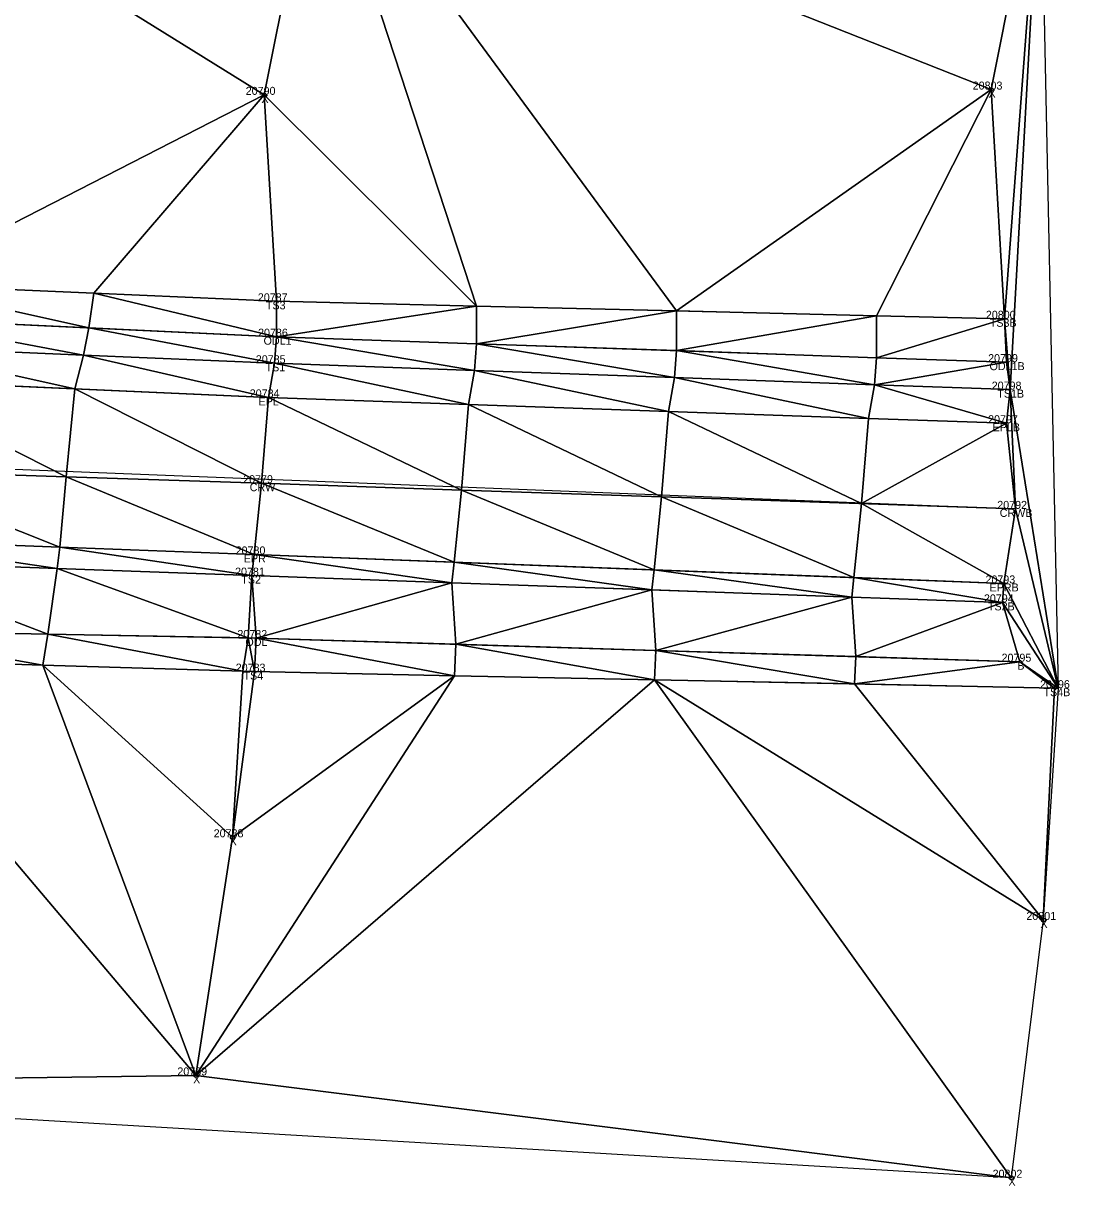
# Model space of a CAD drawing. Extents: x 1966740 to 1969291, y 1117379 to 1118460.
# Drawn here: x 1969160.5 to 1969291.2, y 1117800.2 to 1117945.4 of the extents above; entities that cross this region are included whole.
import ezdxf

# ---------------------------------------------------------------- set-up
doc = ezdxf.new("R2010")
doc.units = 0
for name, color, linetype in [('Level 1', 7, 'Continuous'), ('Level 3', 7, 'Continuous'), ('Level 30', 7, 'Continuous'), ('Level 35', 7, 'Continuous'), ('Level 50', 7, 'Continuous'), ('Level 52', 7, 'Continuous'), ('Level 53', 7, 'Continuous'), ('Level 56', 7, 'Continuous'), ('Level 6', 7, 'Continuous'), ('Level 62', 7, 'Continuous')]:
    doc.layers.add(name, color=color, linetype=linetype)

msp = doc.modelspace()

# ---------------------------------------------------------------- linework, layer by layer
at = {"layer": 'Level 1'}
msp.add_line((1968120.33, 1117930.94), (1969279.02, 1117884.95), dxfattribs=at)
at = {"layer": 'Level 3'}
for points in [[(1968531.49, 1117931.42), (1968682.06, 1117924.3), (1968783.42, 1117919.17), (1968888.7, 1117914.33), (1968991.06, 1117912.02), (1969093.07, 1117907.16), (1969191.83, 1117902.92), (1969283.72, 1117899.63)], [(1968530.54, 1117925.7), (1968681.97, 1117919.01), (1968783.23, 1117915.36), (1968888.64, 1117911.44), (1968991.22, 1117907.09), (1969091.98, 1117903.06), (1969191.09, 1117898.66), (1969283.27, 1117895.43)], [(1968882.13, 1117923.29), (1968991.72, 1117919.56), (1969094.35, 1117914.97), (1969192.08, 1117910.66), (1969282.99, 1117908.48)], [(1968529.36, 1117916.3), (1968681.48, 1117908.5), (1968781.89, 1117904.51), (1968887.49, 1117900.39), (1968989.06, 1117896.4), (1969090.87, 1117891.24), (1969190.23, 1117887.94), (1969284.4, 1117884.73)], [(1968527.82, 1117906.41), (1968680.79, 1117899.07), (1968781.71, 1117895.37), (1968887.86, 1117891.84), (1968988.65, 1117888.23), (1969090.1, 1117882.83), (1969189.3, 1117879.04), (1969282.94, 1117875.42)], [(1968528.99, 1117899.6), (1968680.45, 1117894.84), (1968781.74, 1117892.71), (1968887.7, 1117888.94), (1968987.81, 1117885.08), (1969089.75, 1117880.01), (1969189.02, 1117876.39), (1969282.76, 1117873.05)], [(1968528.68, 1117880.51), (1968680.3, 1117884.55), (1968781.05, 1117880.46), (1968887.57, 1117875.57), (1968986, 1117872.85), (1969087.95, 1117867.56), (1969189.32, 1117864.4), (1969289.73, 1117862.33)]]:
    msp.add_lwpolyline(points, dxfattribs=at)
at = {"layer": 'Level 30'}
for centre in [(1969190.53, 1117936.45), (1969281.34, 1117937.11), (1969186.57, 1117843.71), (1969287.84, 1117833.38), (1969182.01, 1117813.96), (1969283.84, 1117801.18)]:
    msp.add_circle(centre, 0.25, dxfattribs=at)
at = {"layer": 'Level 35'}
for points in [[(1969111.1, 1117985.78), (1969197.32, 1117970.35), (1969190.53, 1117936.45)], [(1969111.1, 1117985.78), (1969190.53, 1117936.45), (1969144.29, 1117912.77)], [(1969190.53, 1117936.45), (1969197.32, 1117970.35), (1969217.07, 1117910.06)], [(1969197.32, 1117970.35), (1969287.52, 1117968.07), (1969281.34, 1117937.11)], [(1969197.32, 1117970.35), (1969281.34, 1117937.11), (1969242.05, 1117909.46)], [(1969197.32, 1117970.35), (1969242.05, 1117909.46), (1969217.07, 1117910.06)], [(1969281.34, 1117937.11), (1969287.52, 1117968.07), (1969282.99, 1117908.48)], [(1969282.99, 1117908.48), (1969287.52, 1117968.07), (1969283.72, 1117899.63)], [(1969283.72, 1117899.63), (1969287.52, 1117968.07), (1969289.73, 1117862.33)], [(1969144.29, 1117912.77), (1969190.53, 1117936.45), (1969169.25, 1117911.66)], [(1969169.25, 1117911.66), (1969190.53, 1117936.45), (1969192.08, 1117910.66)], [(1969190.53, 1117936.45), (1969217.07, 1117910.06), (1969192.08, 1117910.66)], [(1969242.05, 1117909.46), (1969281.34, 1117937.11), (1969267.03, 1117908.86)], [(1969267.03, 1117908.86), (1969281.34, 1117937.11), (1969282.99, 1117908.48)], [(1969143.7, 1117908.53), (1969144.29, 1117912.77), (1969168.66, 1117907.35)], [(1969144.29, 1117912.77), (1969169.25, 1117911.66), (1969168.66, 1117907.35)], [(1969168.66, 1117907.35), (1969169.25, 1117911.66), (1969192.08, 1117906.24)], [(1969169.25, 1117911.66), (1969192.08, 1117910.66), (1969192.08, 1117906.24)], [(1969192.08, 1117906.24), (1969192.08, 1117910.66), (1969217.07, 1117910.06)], [(1969192.08, 1117906.24), (1969217.07, 1117910.06), (1969217.06, 1117905.37)], [(1969217.06, 1117905.37), (1969217.07, 1117910.06), (1969242.05, 1117909.46)], [(1969143.01, 1117905.02), (1969143.7, 1117908.53), (1969167.98, 1117903.95)], [(1969143.7, 1117908.53), (1969168.66, 1117907.35), (1969167.98, 1117903.95)], [(1969217.06, 1117905.37), (1969242.05, 1117909.46), (1969242.03, 1117904.5)], [(1969242.03, 1117904.5), (1969242.05, 1117909.46), (1969267.03, 1117908.86)], [(1969242.03, 1117904.5), (1969267.03, 1117908.86), (1969267.01, 1117903.62)], [(1969267.01, 1117903.62), (1969267.03, 1117908.86), (1969282.99, 1117908.48)], [(1969167.98, 1117903.95), (1969168.66, 1117907.35), (1969191.83, 1117902.92)], [(1969168.66, 1117907.35), (1969192.08, 1117906.24), (1969191.83, 1117902.92)], [(1969267.01, 1117903.62), (1969282.99, 1117908.48), (1969283.24, 1117903.06)], [(1969282.99, 1117908.48), (1969283.72, 1117899.63), (1969283.24, 1117903.06)], [(1969191.83, 1117902.92), (1969192.08, 1117906.24), (1969216.81, 1117902.03)], [(1969192.08, 1117906.24), (1969217.06, 1117905.37), (1969216.81, 1117902.03)], [(1969141.92, 1117900.84), (1969143.01, 1117905.02), (1969166.89, 1117899.73)], [(1969143.01, 1117905.02), (1969167.98, 1117903.95), (1969166.89, 1117899.73)], [(1969216.81, 1117902.03), (1969217.06, 1117905.37), (1969241.78, 1117901.13)], [(1969217.06, 1117905.37), (1969242.03, 1117904.5), (1969241.78, 1117901.13)], [(1969241.78, 1117901.13), (1969242.03, 1117904.5), (1969266.76, 1117900.24)], [(1969242.03, 1117904.5), (1969267.01, 1117903.62), (1969266.76, 1117900.24)], [(1969166.89, 1117899.73), (1969167.98, 1117903.95), (1969191.09, 1117898.66)], [(1969167.98, 1117903.95), (1969191.83, 1117902.92), (1969191.09, 1117898.66)], [(1969191.09, 1117898.66), (1969191.83, 1117902.92), (1969216.07, 1117897.78)], [(1969191.83, 1117902.92), (1969216.81, 1117902.03), (1969216.07, 1117897.78)], [(1969266.76, 1117900.24), (1969267.01, 1117903.62), (1969283.24, 1117903.06)], [(1969266.76, 1117900.24), (1969283.24, 1117903.06), (1969283.72, 1117899.63)], [(1969216.07, 1117897.78), (1969216.81, 1117902.03), (1969241.04, 1117896.91)], [(1969216.81, 1117902.03), (1969241.78, 1117901.13), (1969241.04, 1117896.91)], [(1969140.83, 1117889.58), (1969141.92, 1117900.84), (1969165.8, 1117888.75)], [(1969141.92, 1117900.84), (1969166.89, 1117899.73), (1969165.8, 1117888.75)], [(1969241.04, 1117896.91), (1969241.78, 1117901.13), (1969266.02, 1117896.03)], [(1969241.78, 1117901.13), (1969266.76, 1117900.24), (1969266.02, 1117896.03)], [(1969266.02, 1117896.03), (1969266.76, 1117900.24), (1969283.27, 1117895.43)], [(1969266.76, 1117900.24), (1969283.72, 1117899.63), (1969283.27, 1117895.43)], [(1969165.8, 1117888.75), (1969166.89, 1117899.73), (1969190.23, 1117887.94)], [(1969166.89, 1117899.73), (1969191.09, 1117898.66), (1969190.23, 1117887.94)], [(1969190.23, 1117887.94), (1969191.09, 1117898.66), (1969215.2, 1117887.09)], [(1969191.09, 1117898.66), (1969216.07, 1117897.78), (1969215.2, 1117887.09)], [(1969283.27, 1117895.43), (1969283.72, 1117899.63), (1969284.4, 1117884.73)], [(1969283.72, 1117899.63), (1969289.73, 1117862.33), (1969284.4, 1117884.73)], [(1969215.2, 1117887.09), (1969216.07, 1117897.78), (1969240.18, 1117886.24)], [(1969216.07, 1117897.78), (1969241.04, 1117896.91), (1969240.18, 1117886.24)], [(1969240.18, 1117886.24), (1969241.04, 1117896.91), (1969265.15, 1117885.39)], [(1969241.04, 1117896.91), (1969266.02, 1117896.03), (1969265.15, 1117885.39)], [(1969265.15, 1117885.39), (1969266.02, 1117896.03), (1969283.27, 1117895.43)], [(1969265.15, 1117885.39), (1969283.27, 1117895.43), (1969284.4, 1117884.73)], [(1969140.05, 1117880.92), (1969140.83, 1117889.58), (1969165.02, 1117879.97)], [(1969140.83, 1117889.58), (1969165.8, 1117888.75), (1969165.02, 1117879.97)], [(1969165.02, 1117879.97), (1969165.8, 1117888.75), (1969189.3, 1117879.04)], [(1969165.8, 1117888.75), (1969190.23, 1117887.94), (1969189.3, 1117879.04)], [(1969189.3, 1117879.04), (1969190.23, 1117887.94), (1969214.27, 1117878.07)], [(1969190.23, 1117887.94), (1969215.2, 1117887.09), (1969214.27, 1117878.07)], [(1969214.27, 1117878.07), (1969215.2, 1117887.09), (1969239.24, 1117877.11)], [(1969215.2, 1117887.09), (1969240.18, 1117886.24), (1969239.24, 1117877.11)], [(1969239.24, 1117877.11), (1969240.18, 1117886.24), (1969264.21, 1117876.15)], [(1969240.18, 1117886.24), (1969265.15, 1117885.39), (1969264.21, 1117876.15)], [(1969264.21, 1117876.15), (1969265.15, 1117885.39), (1969282.94, 1117875.42)], [(1969265.15, 1117885.39), (1969284.4, 1117884.73), (1969282.94, 1117875.42)], [(1969282.94, 1117875.42), (1969284.4, 1117884.73), (1969289.73, 1117862.33)], [(1969139.71, 1117878.19), (1969140.05, 1117880.92), (1969164.69, 1117877.28)], [(1969140.05, 1117880.92), (1969165.02, 1117879.97), (1969164.69, 1117877.28)], [(1969164.69, 1117877.28), (1969165.02, 1117879.97), (1969189.02, 1117876.39)], [(1969165.02, 1117879.97), (1969189.3, 1117879.04), (1969189.02, 1117876.39)], [(1969138.55, 1117869.57), (1969139.71, 1117878.19), (1969163.54, 1117869.09)], [(1969139.71, 1117878.19), (1969164.69, 1117877.28), (1969163.54, 1117869.09)], [(1969189.02, 1117876.39), (1969189.3, 1117879.04), (1969213.99, 1117875.5)], [(1969189.3, 1117879.04), (1969214.27, 1117878.07), (1969213.99, 1117875.5)], [(1969213.99, 1117875.5), (1969214.27, 1117878.07), (1969238.96, 1117874.61)], [(1969214.27, 1117878.07), (1969239.24, 1117877.11), (1969238.96, 1117874.61)], [(1969163.54, 1117869.09), (1969164.69, 1117877.28), (1969188.53, 1117868.61)], [(1969164.69, 1117877.28), (1969189.02, 1117876.39), (1969188.53, 1117868.61)], [(1969238.96, 1117874.61), (1969239.24, 1117877.11), (1969263.93, 1117873.72)], [(1969239.24, 1117877.11), (1969264.21, 1117876.15), (1969263.93, 1117873.72)], [(1969188.53, 1117868.61), (1969189.02, 1117876.39), (1969189.53, 1117868.6)], [(1969189.02, 1117876.39), (1969213.99, 1117875.5), (1969189.53, 1117868.6)], [(1969189.53, 1117868.6), (1969213.99, 1117875.5), (1969214.5, 1117867.82)], [(1969213.99, 1117875.5), (1969238.96, 1117874.61), (1969214.5, 1117867.82)], [(1969263.93, 1117873.72), (1969264.21, 1117876.15), (1969282.76, 1117873.05)], [(1969264.21, 1117876.15), (1969282.94, 1117875.42), (1969282.76, 1117873.05)], [(1969282.76, 1117873.05), (1969282.94, 1117875.42), (1969289.73, 1117862.33)], [(1969214.5, 1117867.82), (1969238.96, 1117874.61), (1969239.48, 1117867.05)], [(1969238.96, 1117874.61), (1969263.93, 1117873.72), (1969239.48, 1117867.05)], [(1969239.48, 1117867.05), (1969263.93, 1117873.72), (1969264.46, 1117866.28)], [(1969263.93, 1117873.72), (1969282.76, 1117873.05), (1969264.46, 1117866.28)], [(1969264.46, 1117866.28), (1969282.76, 1117873.05), (1969284.94, 1117865.64)], [(1969282.76, 1117873.05), (1969289.73, 1117862.33), (1969284.94, 1117865.64)], [(1969137.91, 1117866), (1969138.55, 1117869.57), (1969162.89, 1117865.22)], [(1969138.55, 1117869.57), (1969163.54, 1117869.09), (1969162.89, 1117865.22)], [(1969162.89, 1117865.22), (1969163.54, 1117869.09), (1969187.88, 1117864.44)], [(1969163.54, 1117869.09), (1969188.53, 1117868.61), (1969187.88, 1117864.44)], [(1969187.88, 1117864.44), (1969188.53, 1117868.61), (1969189.32, 1117864.4)], [(1969188.53, 1117868.61), (1969189.53, 1117868.6), (1969189.32, 1117864.4)], [(1969189.32, 1117864.4), (1969189.53, 1117868.6), (1969214.3, 1117863.88)], [(1969189.53, 1117868.6), (1969214.5, 1117867.82), (1969214.3, 1117863.88)], [(1969214.3, 1117863.88), (1969214.5, 1117867.82), (1969239.29, 1117863.37)], [(1969214.5, 1117867.82), (1969239.48, 1117867.05), (1969239.29, 1117863.37)], [(1969239.29, 1117863.37), (1969239.48, 1117867.05), (1969264.27, 1117862.86)], [(1969239.48, 1117867.05), (1969264.46, 1117866.28), (1969264.27, 1117862.86)], [(1969089.15, 1117812.7), (1969137.91, 1117866), (1969182.01, 1117813.96)], [(1969137.91, 1117866), (1969162.89, 1117865.22), (1969182.01, 1117813.96)], [(1969162.89, 1117865.22), (1969187.88, 1117864.44), (1969186.57, 1117843.71)], [(1969162.89, 1117865.22), (1969186.57, 1117843.71), (1969182.01, 1117813.96)], [(1969264.27, 1117862.86), (1969264.46, 1117866.28), (1969284.94, 1117865.64)], [(1969264.27, 1117862.86), (1969284.94, 1117865.64), (1969289.25, 1117862.34)], [(1969284.94, 1117865.64), (1969289.73, 1117862.33), (1969289.25, 1117862.34)], [(1969182.01, 1117813.96), (1969186.57, 1117843.71), (1969214.3, 1117863.88)], [(1969182.01, 1117813.96), (1969214.3, 1117863.88), (1969239.29, 1117863.37)], [(1969186.57, 1117843.71), (1969187.88, 1117864.44), (1969189.32, 1117864.4)], [(1969186.57, 1117843.71), (1969189.32, 1117864.4), (1969214.3, 1117863.88)], [(1969182.01, 1117813.96), (1969239.29, 1117863.37), (1969283.84, 1117801.18)], [(1969239.29, 1117863.37), (1969264.27, 1117862.86), (1969287.84, 1117833.38)], [(1969239.29, 1117863.37), (1969287.84, 1117833.38), (1969283.84, 1117801.18)], [(1969264.27, 1117862.86), (1969289.25, 1117862.34), (1969287.84, 1117833.38)], [(1969287.84, 1117833.38), (1969289.25, 1117862.34), (1969289.73, 1117862.33)], [(1969089.15, 1117812.7), (1969182.01, 1117813.96), (1969283.84, 1117801.18)]]:
    msp.add_lwpolyline(points, close=True, dxfattribs=at)
at = {"layer": 'Level 50'}
for centre in [(1969192.08, 1117910.66), (1969282.99, 1117908.48), (1969192.08, 1117906.24), (1969191.83, 1117902.92), (1969283.24, 1117903.06), (1969191.09, 1117898.66), (1969283.72, 1117899.63), (1969283.27, 1117895.43), (1969190.23, 1117887.94), (1969284.4, 1117884.73), (1969189.3, 1117879.04), (1969189.02, 1117876.39), (1969282.94, 1117875.42), (1969282.76, 1117873.05), (1969189.53, 1117868.6), (1969284.94, 1117865.64), (1969189.32, 1117864.4), (1969289.73, 1117862.33)]:
    msp.add_circle(centre, 0.001, dxfattribs=at)
at = {"layer": 'Level 6'}
for points in [[(1968531.76, 1117937.18), (1968682.22, 1117928.11), (1968784.28, 1117924.56), (1968890.2, 1117919.49), (1968991.22, 1117915.37), (1969093.76, 1117910.9), (1969192.08, 1117906.24), (1969283.24, 1117903.06)], [(1968528.55, 1117888.35), (1968679.78, 1117887.39), (1968780.67, 1117884.45), (1968887.36, 1117880.9), (1968987.02, 1117877.31), (1969088.58, 1117870.53), (1969189.53, 1117868.6), (1969284.94, 1117865.64)]]:
    msp.add_lwpolyline(points, dxfattribs=at)

# ---------------------------------------------------------------- texts
at = {"layer": 'Level 52'}
for s, p in [('20803', (1969279.03, 1117937.11)), ('20790', (1969188.24, 1117936.45)), ('20788', (1969184.24, 1117843.71)), ('20801', (1969285.74, 1117833.38)), ('20789', (1969179.7, 1117813.96)), ('20802', (1969281.52, 1117801.18))]:
    msp.add_text(s, height=1, dxfattribs=at).set_placement(p)
at = {"layer": 'Level 53'}
for s, p in [('20787', (1969189.75, 1117910.66)), ('TS3', (1969190.76, 1117909.66)), ('20800', (1969280.68, 1117908.48)), ('20786', (1969189.78, 1117906.24)), ('TS3B', (1969281.17, 1117907.48)), ('ODL1', (1969190.47, 1117905.24)), ('20785', (1969189.5, 1117902.92)), ('TS1', (1969190.72, 1117901.92)), ('20799', (1969280.96, 1117903.06)), ('ODL1B', (1969281.14, 1117902.06)), ('20798', (1969281.41, 1117899.63)), ('20784', (1969188.74, 1117898.66)), ('EPL', (1969189.84, 1117897.66)), ('TS1B', (1969282.11, 1117898.63)), ('20797', (1969280.96, 1117895.43)), ('EPLB', (1969281.52, 1117894.43)), ('20779', (1969187.92, 1117887.94)), ('CRW', (1969188.74, 1117886.94)), ('20792', (1969282.1, 1117884.73)), ('CRWB', (1969282.41, 1117883.73)), ('20780', (1969186.98, 1117879.04)), ('EPR', (1969188, 1117878.04)), ('20781', (1969186.91, 1117876.39)), ('TS2', (1969187.69, 1117875.39)), ('20793', (1969280.63, 1117875.42)), ('EPRB', (1969281.14, 1117874.42)), ('20794', (1969280.44, 1117873.05)), ('TS2B', (1969280.94, 1117872.05)), ('20783', (1969186.99, 1117864.4)), ('TS4', (1969187.97, 1117863.4)), ('20796', (1969287.45, 1117862.33)), ('TS4B', (1969287.88, 1117861.33))]:
    msp.add_text(s, height=1, dxfattribs=at).set_placement(p)
at = {"layer": 'Level 56'}
for s, p in [('20782', (1969187.2, 1117868.6)), ('ODL', (1969188.2, 1117867.6)), ('20795', (1969282.64, 1117865.64)), ('B', (1969284.61, 1117864.64))]:
    msp.add_text(s, height=1, dxfattribs=at).set_placement(p)
at = {"layer": 'Level 62'}
for p in [(1969190.2, 1117935.45), (1969281.01, 1117936.11), (1969186.23, 1117842.71), (1969287.5, 1117832.38), (1969181.67, 1117812.96), (1969283.5, 1117800.18)]:
    msp.add_text('X', height=1, dxfattribs=at).set_placement(p)

doc.saveas('drawing.dxf')
